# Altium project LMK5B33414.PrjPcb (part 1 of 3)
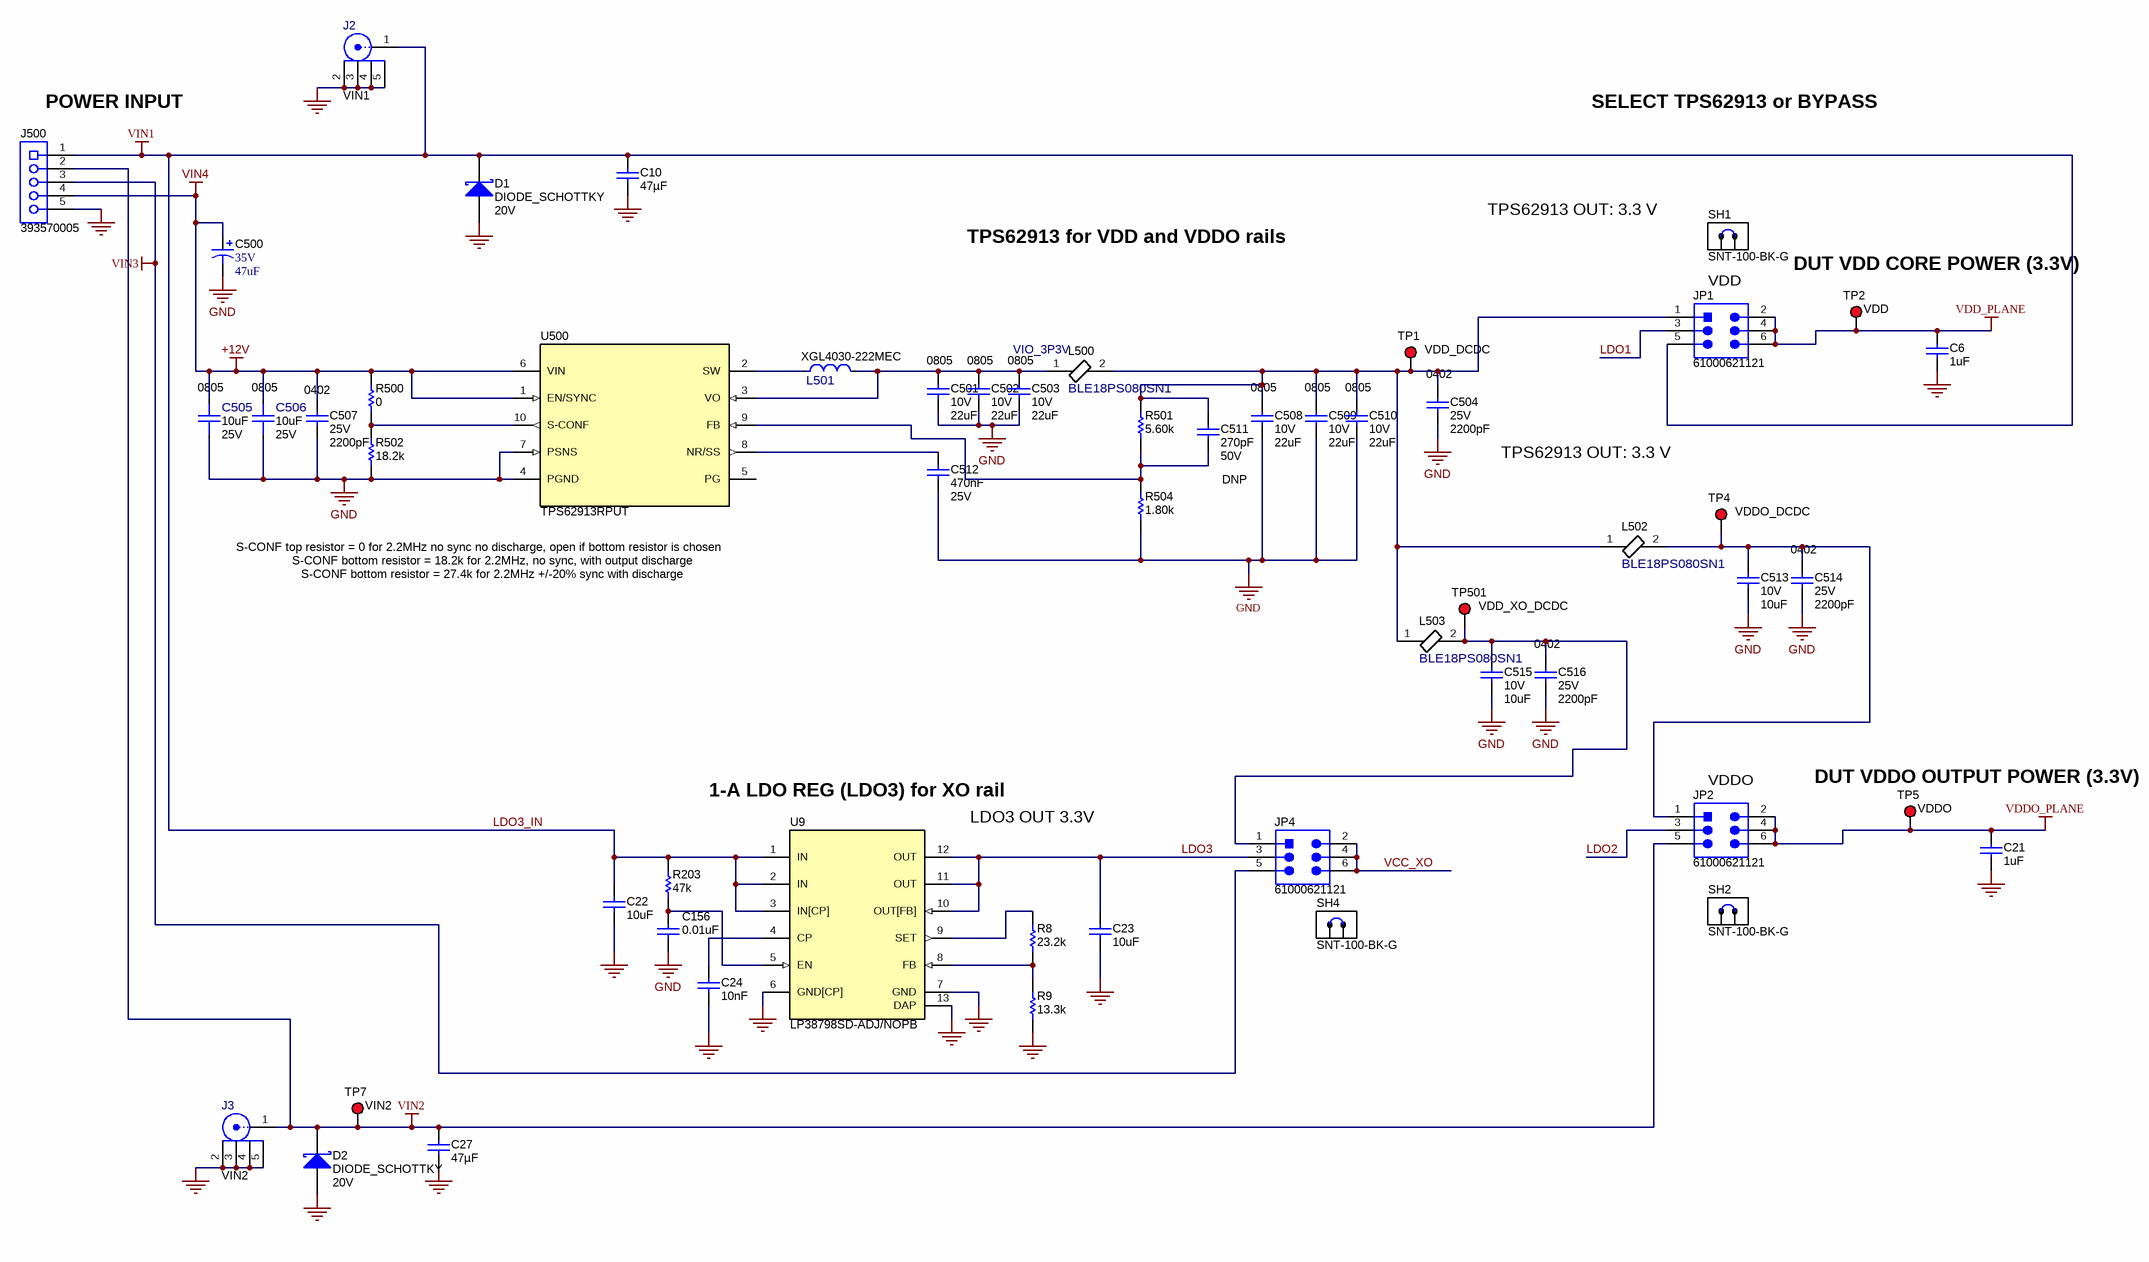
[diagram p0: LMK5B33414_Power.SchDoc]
TID: N/A; TechSupport: http://www.ti.com/support; SCH_Rev: A; PRJ_Title: LMK5B33414; PRJ_Customer: Public Release; PCB_Rev: A; CopyrightYear: 2021
11 sheets, 518 parts. Net scope: global (net labels, ports and power ports of the same name join across sheets).
Board file: LMK5B33414_PCB.PcbDoc
Sheets:
  LMK5B33414_Power.SchDoc
  LMK5B33414_Power_Alternate.SchDoc
  LMK5B33414_PowerDist.SchDoc
  LMK5B33414_DUT.SchDoc
  LMK5B33414_Logic.SchDoc
  LMK5B33414_Outputs_A.SchDoc
  LMK5B33414_Outputs_B.SchDoc
  LMK5B33414_Outputs_C.SchDoc
  LMK5B33414_XO.SchDoc
  LMK5B33414_USB2ANY.SchDoc
  LMK5B33414_Hardware.SchDoc

## Sheet LMK5B33414_Power.SchDoc
size C; Date: Not shown in title block; ApprovedBy: Not shown in title block; CheckedBy: Not shown in title block; Author: Not shown in title block; CompanyName: Not shown in title block; Engineer: Not shown in title block; Organization: Not shown in title block; Address1: Not shown in title block; Address2: Not shown in title block; Address3: Not shown in title block; Address4: Not shown in title block; DocumentNumber: 2; Revision: Use project parameter SCH_Rev; SheetNumber: 2; SheetTotal: 3; PageSetup: Record=PageOptions¦CenterHorizontal=True¦CenterVertical=True¦PrintScale=1.00¦XCorrection=1.00¦YCorrection=1.00¦PrintKind=0¦BorderSize=5000000¦LeftOffset=0¦BottomOffset=0¦Orientation=2¦PaperLength=1000¦PaperWidth=1000¦Scale=100¦PaperSource=15¦PrintQuality=600¦MediaType=1¦DitherType=10¦PaperKind=Letter¦PrintScaleMode=1

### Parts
C6  ValueDisplayed: 1uF  [0603]  (hidden comment: Capacitor)
C10  ValueDisplayed: 47µF  [0805_HV]  (hidden comment: GRM21BR61A476ME15L)
C21  ValueDisplayed: 1uF  [0603]  (hidden comment: Capacitor)
C22  ValueDisplayed: 10uF  [0603]  (hidden comment: Capacitor)
C23  ValueDisplayed: 10uF  [0603]  (hidden comment: Capacitor)
C24  ValueDisplayed: 10nF  [0603]  (hidden comment: Capacitor)
C27  ValueDisplayed: 47µF  [0805_HV]  (hidden comment: GRM21BR61A476ME15L)
C156  ValueDisplayed: 0.01uF  [0603]  (hidden comment: Capacitor)
C500  VDC_V: 35V  ValueDisplayed: 47uF  [7343-43]  (hidden comment: T495X476K035ATE300)
C501  Cap_Case: 0805  VDC_V: 10V  ValueDisplayed: 22uF  [0805L]  (hidden comment: C2012X7S1A226M125AC)
C502  Cap_Case: 0805  VDC_V: 10V  ValueDisplayed: 22uF  [0805L]  (hidden comment: C2012X7S1A226M125AC)
C503  Cap_Case: 0805  VDC_V: 10V  ValueDisplayed: 22uF  [0805L]  (hidden comment: C2012X7S1A226M125AC)
C504  VDC_V: 25V  ValueDisplayed: 2200pF  [0402]  (hidden comment: GRM155R71E222KA01D)
C505  PackageReference: 0805  ValueDisplayed: 10uF  VDC_V: 25V  [FP-C2012X7S1E106K125AC_0805-MFG]  (hidden comment: C2012X7S1E106K125AC)
C506  PackageReference: 0805  ValueDisplayed: 10uF  VDC_V: 25V  [FP-C2012X7S1E106K125AC_0805-MFG]  (hidden comment: C2012X7S1E106K125AC)
C507  VDC_V: 25V  ValueDisplayed: 2200pF  [0402]  (hidden comment: GRM155R71E222KA01D)
C508  Cap_Case: 0805  VDC_V: 10V  ValueDisplayed: 22uF  [0805L]  (hidden comment: C2012X7S1A226M125AC)
C509  Cap_Case: 0805  VDC_V: 10V  ValueDisplayed: 22uF  [0805L]  (hidden comment: C2012X7S1A226M125AC)
C510  Cap_Case: 0805  VDC_V: 10V  ValueDisplayed: 22uF  [0805L]  (hidden comment: C2012X7S1A226M125AC)
C511  Cap_F: 270pF  VDC_V: 50V  [0402]  (hidden comment: UMK105CG271JV-F)
C512  Cap_F: 470nF  VDC_V: 25V  [0603]  (hidden comment: C1608X7R1E474K080AE)
C513  VDC_V: 10V  ValueDisplayed: 10uF  [0603]  (hidden comment: GRM188Z71A106MA73D)
C514  VDC_V: 25V  ValueDisplayed: 2200pF  [0402]  (hidden comment: GRM155R71E222KA01D)
C515  VDC_V: 10V  ValueDisplayed: 10uF  [0603]  (hidden comment: GRM188Z71A106MA73D)
C516  VDC_V: 25V  ValueDisplayed: 2200pF  [0402]  (hidden comment: GRM155R71E222KA01D)
D1  DIODE_SCHOTTKY  value 20V  [SMA]
D2  DIODE_SCHOTTKY  value 20V  [SMA]
J2  VIN1  [FP-CON-SMA-EDGE-S_CONN_JACK-MFG]
J3  VIN2  [FP-CON-SMA-EDGE-S_CONN_JACK-MFG]
J500  393570005  [Molex_0393570005]
JP1  61000621121  [Wurth_61000621121]
JP2  61000621121  [Wurth_61000621121]
JP4  61000621121  [Wurth_61000621121]
L500  BLE18PS080SN1  [FP-BLE18PS080SN1_0603-MFG]
L501  XGL4030-222MEC  [FP-XGL4030-222MEC_SMT_IND_4MM0_4MM0-MFG]
L502  BLE18PS080SN1  [FP-BLE18PS080SN1_0603-MFG]
L503  BLE18PS080SN1  [FP-BLE18PS080SN1_0603-MFG]
R8  ValueDisplayed: 23.2k  [0603]  (hidden comment: CRCW060323K2FKEA)
R9  ValueDisplayed: 13.3k  [0603]  (hidden comment: CRCW060313K3FKEA)
R203  ValueDisplayed: 47k  [0603]  (hidden comment: Resistor)
R500  ValueDisplayed: 0  [0603]  (hidden comment: ERJ-3GEY0R00V)
R501  ValueDisplayed: 5.60k  [0603]  (hidden comment: RG1608P-562-B-T5)
R502  ValueDisplayed: 18.2k  [0603]  (hidden comment: CRCW060318K2FKEA)
R504  ValueDisplayed: 1.80k  [0603]  (hidden comment: RT0603BRD071K8L)
SH1  SNT-100-BK-G  [SNT-100-BK-G]
SH2  SNT-100-BK-G  [SNT-100-BK-G]
SH4  SNT-100-BK-G  [SNT-100-BK-G]
TP1  VDD_DCDC  [Keystone5000]
TP2  VDD  [Keystone5000]
TP4  VDDO_DCDC  [Keystone5000]
TP5  VDDO  [Keystone5000]
TP7  VIN2  [Keystone5000]
TP501  VDD_XO_DCDC  [Keystone5000]
U9  LP38798SD-ADJ/NOPB  [DNT0012B]
U500  TPS62913RPUT  [RPU0010A]

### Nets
+12V: C500.1(+) C505.2 C506.2 C507.1 J500.4 R500.2 U500.1(EN/SYNC) U500.6(VIN)  [also labelled VIN4]
GND: C6.1 C10.2 C21.1 C22.2 C23.2 C24.2 C27.2 C156.2 C500.2(-) C501.2 C502.2 C503.2 C504.2 C505.1 C506.1 C507.2 C508.2 C509.2 C510.2 C512.2 C513.2 C514.2 C515.2 C516.2 D1.2(A) D2.2(A) J2.2 J2.3 J2.4 J2.5 J3.2 J3.3 J3.4 J3.5 J500.5 R9.1 R502.1 R504.1 U9.6(GND[CP]) U9.7(GND) U9.13(DAP) U500.4(PGND) U500.7(PSNS)
LDO3_IN: C10.1 C22.1 D1.1(K) J2.1 J500.1 JP1.5 R203.1 U9.1(IN) U9.2(IN) U9.3(IN[CP])  [also labelled VIN1]
VCC_XO: JP4.2 JP4.4 JP4.6
VDD_PLANE: C6.2 JP1.2 JP1.4 JP1.6 TP2.1
VDDO_PLANE: C21.2 JP2.2 JP2.4 JP2.6 TP5.1
VIN2: C27.1 D2.1(K) J3.1 J500.2 JP2.5 TP7.1
VIN3: J500.3 JP4.5
LDO1: JP1.3
LDO2: JP2.3
LDO3: C23.1 JP4.3 U9.10(OUT[FB]) U9.11(OUT) U9.12(OUT)
NetC24_1: C24.1 U9.4(CP)
NetC156_1: C156.1 R203.2 U9.5(EN)
NetC501_1: C501.1 C502.1 C503.1 L500.1 L501.2 U500.3(VO)
NetC504_1: C504.1 C508.1 C509.1 C510.1 C511.1 JP1.1 L500.2 L502.1 L503.1 R501.2 TP1.1
NetC511_2: C511.2 R501.1 R504.2 U500.9(FB)
NetC512_1: C512.1 U500.8(NR/SS)
NetC513_1: C513.1 C514.1 JP2.1 L502.2 TP4.1
NetC515_1: C515.1 C516.1 JP4.1 L503.2 TP501.1
NetL501_1: L501.1 U500.2(SW)
NetR8_1: R8.1 R9.2 U9.8(FB)
NetR8_2: R8.2 U9.9(SET)
NetR500_1: R500.1 R502.2 U500.10(S-CONF)

Not connected (* = marked no-connect by the designer): U500 5(PG)

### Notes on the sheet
- (near J500) POWER INPUT
- SELECT TPS62913 or BYPASS
- TPS62913 for VDD and VDDO rails
- TPS62913 OUT: 3.3 V
- (near TP2) DUT VDD CORE POWER (3.3V)
- VDD
- VIO_3P3V
- DNP
- S-CONF top resistor = 0 for 2.2MHz no sync no discharge, open if bottom resistor is chosen
- S-CONF bottom resistor = 18.2k for 2.2MHz, no sync, with output discharge
- S-CONF bottom resistor = 27.4k for 2.2MHz +/-20% sync with discharge
- 1-A LDO REG (LDO3) for XO rail
- (near JP2) VDDO
- (near TP5) DUT VDDO OUTPUT POWER (3.3V)
- LDO3 OUT 3.3V

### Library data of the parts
C6 C21 = CMP-0006869-5: CAP, CERM, 1 uF, 10 V, +/- 10%, X5R, 0603; Manufacturer: Kemet; PartNumber: C0603C105K8PACTU; Polarized: N; TaMax_C: 85°C; TaMin_C: -55°C; VDC_V: 10V; Cap_F: 1µF; Value: 1uF; Value1: Unknown; AEC Category: Q200; SizeArea_mm2: 1.28; SizeAreaWB_mm2: 4.68; SizeX_mm: 1.6; SizeY_mm: 0.8; SizeZ_mm: 1; U/M: EA
C10 C27 = CMP-0078699-1: CAP, CERM, 47 µF, 10 V,+/- 20%, X5R, 0805; Manufacturer: MuRata; Polarized: N; Value: 47uF; U/M: EA; VDC_V: 10V; TaMin_C: -55°C; TaMax_C: 85°C; Cap_Case: 0805; SizeArea_mm2: 2.5; SizeAreaWB_mm2: 6.75; SizeX_mm: 2; SizeY_mm: 1.25; SizeZ_mm: 1.45; AEC Category: Q200; Green_Lifecycle: Active; Green_REACh: Passed
C22-C24 = CMP-0007003-5: CAP, CERM, 10 uF, 10 V, +/- 20%, X5R, 0603; PartNumber: C1608X5R1A106M080AC; Manufacturer: TDK; Polarized: N; Value: 10uF; U/M: EA; Cap_F: 10µF; ESR_ohm: 7.8m; Value1: 0.0078 ohm; VDC_V: 10V; IRMS_A: 1.85A; TaMin_C: -55°C; TaMax_C: 85°C; SizeArea_mm2: 1.28; SizeAreaWB_mm2: 4.68; SizeX_mm: 1.6; SizeY_mm: 0.8; SizeZ_mm: 1; AEC Category: Q200
C156 = CMP-0006850-4: CAP, CERM, 0.01 uF, 50 V, +/- 5%, X7R, 0603; PartNumber: C0603C103J5RACTU; Manufacturer: Kemet; Polarized: N; Value: 0.01uF; U/M: EA; Cap_F: 10nF; Value1: Unknown; VDC_V: 50V; TaMin_C: -55°C; TaMax_C: 125°C; SizeArea_mm2: 1.28; SizeAreaWB_mm2: 4.68; SizeX_mm: 1.6; SizeY_mm: 0.8; SizeZ_mm: 1; AEC Category: Q200
C500 = CMP-0011835-2: CAP, TA, 47 uF, 35 V, +/- 10%, 0.3 ohm, SMD; Manufacturer: Kemet; TaMin_C: -55°C; ESR_ohm: 3d; Polarized: Y; SizeAreaWB_mm2: 58.59; Value1: 0.3 ohm; U/M: EA; Value: 47uF; TaMax_C: 125°C; SizeZ_mm: 4.3; SizeX_mm: 7.3; Cap_Case: X; SizeArea_mm2: 31.39; CompType: Capacitor; Cap_F: 47µF; IRMS_A: 6.67dA; AEC Category: Q200
C501-C503 C508-C510 = CMP-0007890-1: CAP, CERM, 22 uF, 10 V, +/- 20%, X7S, 0805; Manufacturer: TDK; TaMin_C: -55°C; ESR_ohm: 2.05m; Polarized: N; SizeAreaWB_mm2: 6.75; Value1: 0.00205 ohm; U/M: EA; Value: 22uF; TaMax_C: 125°C; SizeZ_mm: 1.45; SizeX_mm: 2; SizeY_mm: 1.25; SizeArea_mm2: 2.5; Cap_F: 22µF; IRMS_A: 4.55587A; AEC Category: Q200
C504 C507 C514 C516 = CMP-0006663-2: CAP, CERM, 2200 pF, 25 V, +/- 10%, X7R, 0402; Manufacturer: MuRata; TaMin_C: -55°C; Polarized: N; SizeAreaWB_mm2: 3; Value1: Unknown; U/M: EA; Value: 2200pF; TaMax_C: 125°C; SizeZ_mm: 0.6; SizeX_mm: 1; SizeY_mm: 0.5; Cap_F: 2.2nF; AEC Category: Q200
C505 C506 = CMP-0089528-1: 10µF ±10% 25V Ceramic Capacitor X7S 0805 (2012 Metric); Manufacturer: TDK; TempCo: 22%; SizeZ_mm: 1.5mm; AEC Qualified: No
C511 = CMP-0087076-3: CAP CER 270PF 50V NP0 0402; Manufacturer: Taiyo Yuden; Tolerance_%: 5%; SizeZ_mm: 0.55mm; AEC Qualified: No; TempCo: 30ppm/°C
C512 = CMP-0750175-1: CAP, CERM, 0.47 µF, 25 V,+/- 10%, X7R, 0603; Manufacturer: TDK; AEC Qualified: N; TaMax_C: 125°C; U/M: EA; AEC Category: Q200; Value: 0.47uF; SizeX_mm: 1.6; SizeAreaWB_mm2: 4.68; SizeZ_mm: 1; SizeY_mm: 0.8; SizeArea_mm2: 1.28; ValueDisplayed: 0.47µF; TaMin_C: -55°C
C513 C515 = CMP-0007497-5: CAP, CERM, 10 uF, 10 V, +/- 20%, X7R, 0603; Manufacturer: MuRata; TaMin_C: -55°C; Polarized: N; SizeAreaWB_mm2: 4.68; Value1: Unknown; U/M: EA; Value: 10uF; TaMax_C: 125°C; SizeZ_mm: 1; SizeX_mm: 1.6; SizeY_mm: 0.8; SizeArea_mm2: 1.28; Cap_F: 10µF; AEC Category: Q200
D1 D2 = CMP-0028399-2: Diode, Schottky, 20 V, 2 A, SMA; PartNumber: B220A-13-F; Manufacturer: Diodes Inc.; Vf_V: 5dV; Value1: 2A; Value2: 0.5V; TJmax_C: 150°C; RJC_CperW: 20; AEC Category: Q101; Green_Lifecycle: Active; Green_REACh: Passed; SizeArea_mm2: 16.3228; SizeAreaWB_mm2: 37.3428; SizeX_mm: 5.59; SizeY_mm: 2.92; SizeZ_mm: 2.87
J2 J3 = CMP-0088000-4: CONN SMA JACK STR EDGE MNT; Manufacturer: RF Solutions Ltd.; PartNumber: CON-SMA-EDGE-S; ContactFinish: Gold; Shrouded: true
J500 = CMP-0080926-1: Terminal Block, 3.5mm, 5x1, Tin, TH; Manufacturer: Molex; Pitch_mm: 3.5; Gender: Female; Voltage_V: 300V; Row_Count: 1; Current_A: 17.5A; Cert_UL: Y
JP1 JP2 JP4 = CMP-0079534-2: Header, 2.54mm, 3x2, Gold, SMT; Manufacturer: Wurth Elektronik; Pitch_mm: 2.54; Gender: Male; Cert_UL: Y; Current_A: 3A; Voltage_V: 250V; Shrouded: N; Row_Count: 2
L500 L502 L503 = CMP-0087072-1: Bead inductor BLE series, 8A; Manufacturer: Murata; SizeZ_mm: 0.75mm; AEC Qualified: No; Material: Ferrite
L501 = CMP-0089541-1: Inductor Power Shielded Wirewound 2.2uH 20% 1MHz Composite 8.7A 15mOhm DCR Automotive T/R; Manufacturer: Coilcraft; Shrouded: true; SizeZ_mm: 3.1mm; AEC Grade: Grade 1; AEC Qualified: Yes; Isat: 3.1A; Ind_H: 2.2µH; Self Resonant Frequency: 40MHz; DCR_ohm: 0.015; Standoff Height: 0.16mm; TaMin_C: -40°C; TaMax_C: +125°C
R8 = CMP-0022228-4: RES, 23.2 k, 1%, 0.1 W, AEC-Q200 Grade 0, 0603; Manufacturer: Vishay-Dale; Value: 23.2k; Value_Code: 23k2; Power_W: 100mW; Value2: 0.1W; VDC_V: 75V; TempCo: 100 ppm/C; EIA_Code: E96; SizeArea_mm2: 1.28; SizeX_mm: 1.6; SizeY_mm: 0.8; SizeZ_mm: 1; AEC Category: Q200; AEC Qualified: Y; AEC Grade: 0
R9 = CMP-0022043-4: RES, 13.3 k, 1%, 0.1 W, AEC-Q200 Grade 0, 0603; Manufacturer: Vishay-Dale; Value: 13.3k; Value_Code: 13k3; Power_W: 100mW; Value2: 0.1W; VDC_V: 75V; TempCo: 100 ppm/C; EIA_Code: E96; SizeArea_mm2: 1.28; SizeX_mm: 1.6; SizeY_mm: 0.8; SizeZ_mm: 1; AEC Category: Q200; AEC Qualified: Y; AEC Grade: 0
R203 = CMP-0025814-4: RES, 47 k, 5%, 0.1 W, AEC-Q200 Grade 0, 0603; PartNumber: CRCW060347K0JNEA; Manufacturer: Vishay-Dale; Value: 47k; Value_Code: 47k0; Power_W: 100mW; Value2: 0.1W; VDC_V: 75V; TempCo: 200 ppm/C; EIA_Code: E24; SizeArea_mm2: 1.28; SizeX_mm: 1.6; SizeY_mm: 0.8; SizeZ_mm: 1; AEC Category: Q200; AEC Qualified: Y; AEC Grade: 0
R500 = CMP-0025874-4: RES, 0, 5%, 0.1 W, AEC-Q200 Grade 0, 0603; Manufacturer: Panasonic; Power_W: 100mW; TempCo: 600 ppm/C; Value_Code: 0000; Value: 0; EIA_Code: E24; SizeX_mm: 1.6; SizeY_mm: 0.8; SizeZ_mm: 1; Value2: 0.1W; SizeArea_mm2: 1.28; AEC Qualified: Y; VDC_V: 50V; AEC Category: Q200; SizeAreaWB_mm2: 4.68
R501 = CMP-0023576-3: RES, 5.60 k, 0.1%, 0.1 W, 0603; Manufacturer: Susumu Co Ltd; Power_W: 100mW; TempCo: 25 ppm/C; Value_Code: 5k60; U/M: EA; Value: 5.60k; Res_ohm: 5.6k; SizeX_mm: 1.6; SizeY_mm: 0.8; SizeZ_mm: 1; Value2: 0.1W; SizeArea_mm2: 1.28; VDC_V: 75V; AEC Category: Q200
R502 = CMP-0022097-4: RES, 18.2 k, 1%, 0.1 W, AEC-Q200 Grade 0, 0603; Manufacturer: Vishay-Dale; Power_W: 100mW; TempCo: 100 ppm/C; Value_Code: 18k2; Value: 18.2k; EIA_Code: E96; SizeX_mm: 1.6; SizeY_mm: 0.8; SizeZ_mm: 1; Value2: 0.1W; SizeArea_mm2: 1.28; AEC Qualified: Y; VDC_V: 75V; AEC Category: Q200; AEC Grade: 0
R504 = CMP-0023914-3: RES, 1.80 k, 0.1%, 0.1 W, 0603; Manufacturer: Yageo America; Power_W: 100mW; TempCo: 25 ppm/C; Value_Code: 1k80; U/M: EA; Value: 1.80k; EIA_Code: E192; Res_ohm: 1.8k; SizeX_mm: 1.6; SizeY_mm: 0.8; SizeZ_mm: 1; Value2: 0.1W; SizeArea_mm2: 1.28; VDC_V: 75V; AEC Category: Q200
SH1 SH2 SH4 = CMP-0003623-3: Shunt, 100mil, Gold plated, Black; Manufacturer: Samtec; Alternate Manufacturer: 3M; Alternate PartNumber: 969102-0000-DA; Value: 1x2; Note: You can "mate" this to a header by matching the designator.  i.e. use SH-J3 for header J3
TP1 TP2 TP4 TP5 TP7 TP501 = CMP-0055137-1: Test Point, Miniature, Red, TH; Manufacturer: Keystone; CNHeader: FALSE; ContactFinish: Silver; CT: TRUE; Green_Lifecycle: Active; Green_REACh: Passed
U9 = CMP-0066007-2: 800-mA Ultra-Low-Noise, High-PSRR LDO, DNT0012B (WSON-12); Manufacturer: Texas Instruments; SizeZ_mm: 0.8; SizeX_mm: 4.0; SizeArea_mm2: 16.0; CompType: IC; U/M: EA; SizeAreaWB_mm2: 25.0
U500 = CMP-0860321-2: 3A Low Noise and Low Ripple buck converter, RPU0010A (VQFN-10); Alternate Manufacturer: Texas Instruments; SizeArea_mm2: 4; SizeAreaWB_mm2: 9; AEC Category: Q200; SizeY_mm: 2; CompType: IC; SizeZ_mm: 1; AEC Qualified: N

## Sheet LMK5B33414_Power_Alternate.SchDoc
size B; Date: Not shown in title block; ApprovedBy: Not shown in title block; CheckedBy: Not shown in title block; Author: Not shown in title block; CompanyName: Not shown in title block; Engineer: Not shown in title block; Organization: Not shown in title block; Address1: Not shown in title block; Address2: Not shown in title block; Address3: Not shown in title block; Address4: Not shown in title block; DocumentNumber: 2; Revision: Use project parameter SCH_Rev; SheetNumber: 2; SheetTotal: 3; PageSetup: Record=PageOptions¦CenterHorizontal=True¦CenterVertical=True¦PrintScale=1.00¦XCorrection=1.00¦YCorrection=1.00¦PrintKind=0¦BorderSize=5000000¦LeftOffset=0¦BottomOffset=0¦Orientation=2¦PaperLength=1000¦PaperWidth=1000¦Scale=100¦PaperSource=15¦PrintQuality=600¦MediaType=1¦DitherType=10¦PaperKind=Letter¦PrintScaleMode=1
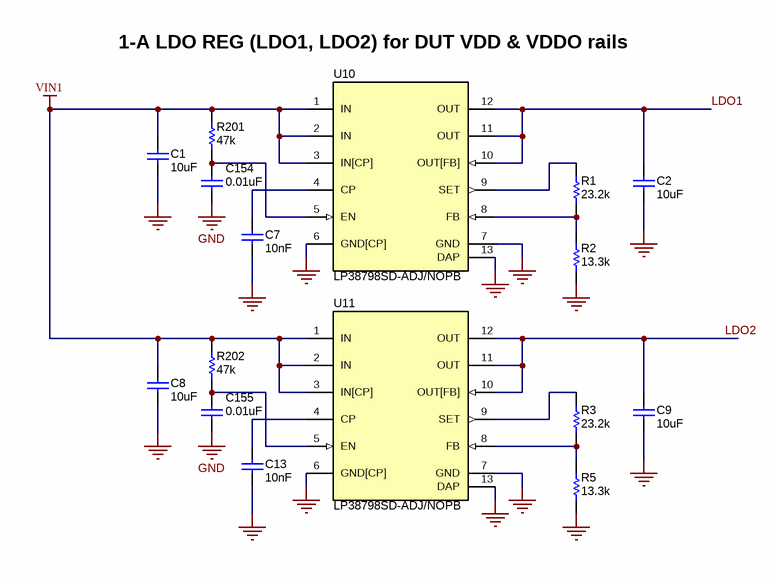
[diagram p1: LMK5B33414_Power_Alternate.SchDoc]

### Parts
C1  ValueDisplayed: 10uF  [0603]  (hidden comment: Capacitor)
C2  ValueDisplayed: 10uF  [0603]  (hidden comment: Capacitor)
C7  ValueDisplayed: 10nF  [0603]  (hidden comment: Capacitor)
C8  ValueDisplayed: 10uF  [0603]  (hidden comment: Capacitor)
C9  ValueDisplayed: 10uF  [0603]  (hidden comment: Capacitor)
C13  ValueDisplayed: 10nF  [0603]  (hidden comment: Capacitor)
C154  ValueDisplayed: 0.01uF  [0603]  (hidden comment: Capacitor)
C155  ValueDisplayed: 0.01uF  [0603]  (hidden comment: Capacitor)
R1  ValueDisplayed: 23.2k  [0603]  (hidden comment: CRCW060323K2FKEA)
R2  ValueDisplayed: 13.3k  [0603]  (hidden comment: CRCW060313K3FKEA)
R3  ValueDisplayed: 23.2k  [0603]  (hidden comment: CRCW060323K2FKEA)
R5  ValueDisplayed: 13.3k  [0603]  (hidden comment: CRCW060313K3FKEA)
R201  ValueDisplayed: 47k  [0603]  (hidden comment: Resistor)
R202  ValueDisplayed: 47k  [0603]  (hidden comment: Resistor)
U10  LP38798SD-ADJ/NOPB  [DNT0012B]
U11  LP38798SD-ADJ/NOPB  [DNT0012B]

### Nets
GND: C1.2 C2.2 C7.2 C8.2 C9.2 C13.2 C154.2 C155.2 R2.1 R5.1 U10.6(GND[CP]) U10.7(GND) U10.13(DAP) U11.6(GND[CP]) U11.7(GND) U11.13(DAP)
VIN1: C1.1 C8.1 R201.1 R202.1 U10.1(IN) U10.2(IN) U10.3(IN[CP]) U11.1(IN) U11.2(IN) U11.3(IN[CP])  [project net LDO3_IN]
LDO1: C2.1 U10.10(OUT[FB]) U10.11(OUT) U10.12(OUT)
LDO2: C9.1 U11.10(OUT[FB]) U11.11(OUT) U11.12(OUT)
NetC7_1: C7.1 U10.4(CP)
NetC13_1: C13.1 U11.4(CP)
NetC154_1: C154.1 R201.2 U10.5(EN)
NetC155_1: C155.1 R202.2 U11.5(EN)
NetR1_1: R1.1 R2.2 U10.8(FB)
NetR1_2: R1.2 U10.9(SET)
NetR3_1: R3.1 R5.2 U11.8(FB)
NetR3_2: R3.2 U11.9(SET)

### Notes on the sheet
- 1-A LDO REG (LDO1, LDO2) for DUT VDD & VDDO rails

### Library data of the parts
C1 C2 C7-C9 C13 = CMP-0007003-5: as C22 on sheet LMK5B33414_Power
C154 C155 = CMP-0006850-4: as C156 on sheet LMK5B33414_Power
R1 R3 = CMP-0022228-4: as R8 on sheet LMK5B33414_Power
R2 R5 = CMP-0022043-4: as R9 on sheet LMK5B33414_Power
R201 R202 = CMP-0025814-4: as R203 on sheet LMK5B33414_Power
U10 U11 = CMP-0066007-2: as U9 on sheet LMK5B33414_Power

## Sheet LMK5B33414_PowerDist.SchDoc
size C; Date: Not shown in title block; ApprovedBy: Not shown in title block; CheckedBy: Not shown in title block; Author: Not shown in title block; CompanyName: Not shown in title block; Engineer: Not shown in title block; Organization: Not shown in title block; Address1: Not shown in title block; Address2: Not shown in title block; Address3: Not shown in title block; Address4: Not shown in title block; DocumentNumber: 2; Revision: Use project parameter SCH_Rev; SheetNumber: 2; SheetTotal: 3; PageSetup: Record=PageOptions¦CenterHorizontal=True¦CenterVertical=True¦PrintScale=1.00¦XCorrection=1.00¦YCorrection=1.00¦PrintKind=0¦BorderSize=5000000¦LeftOffset=0¦BottomOffset=0¦Orientation=2¦PaperLength=1000¦PaperWidth=1000¦Scale=100¦PaperSource=15¦PrintQuality=600¦MediaType=1¦DitherType=10¦PaperKind=Letter¦PrintScaleMode=1
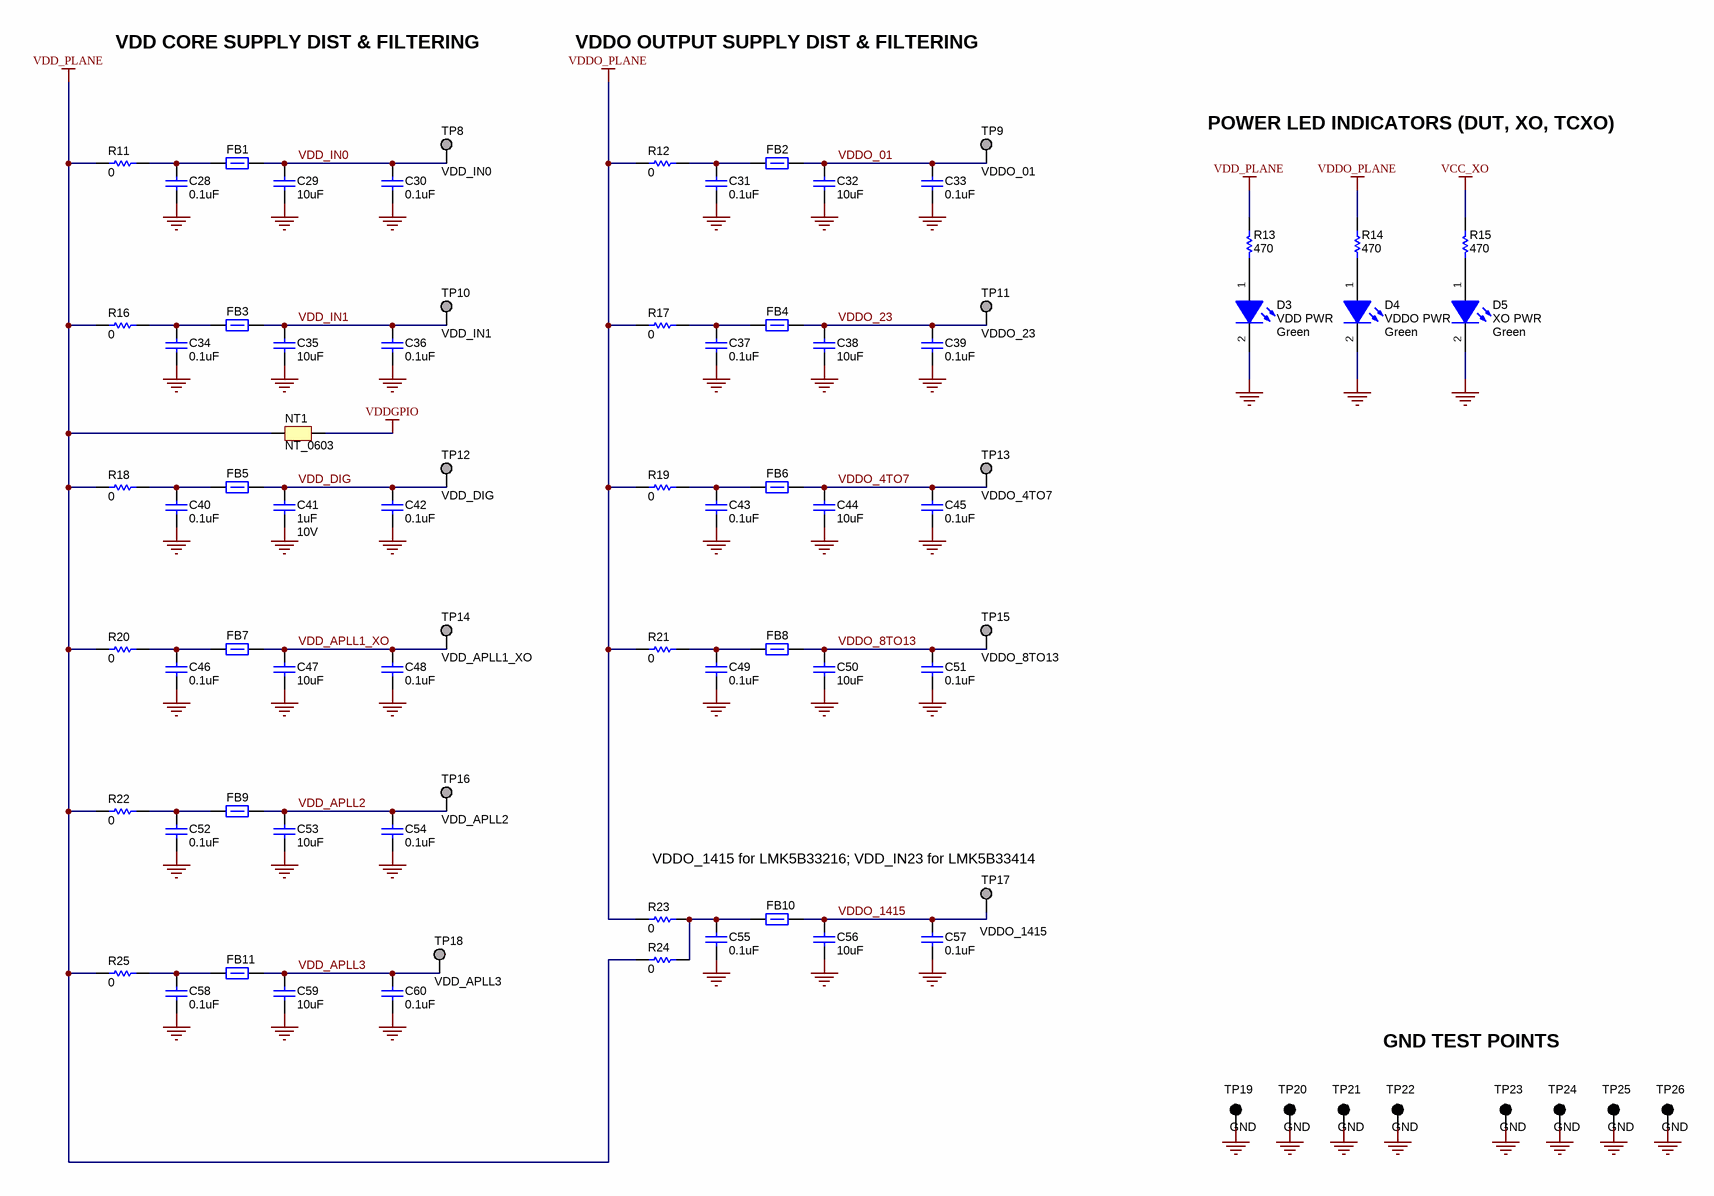
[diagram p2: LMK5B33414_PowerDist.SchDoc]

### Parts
C28  ValueDisplayed: 0.1uF  [0603L]  (hidden comment: Capacitor)
C29  ValueDisplayed: 10uF  [0603L]  (hidden comment: Capacitor)
C30  ValueDisplayed: 0.1uF  [0402L]  (hidden comment: Capacitor)
C31  ValueDisplayed: 0.1uF  [0603L]  (hidden comment: Capacitor)
C32  ValueDisplayed: 10uF  [0603L]  (hidden comment: Capacitor)
C33  ValueDisplayed: 0.1uF  [0402L]  (hidden comment: Capacitor)
C34  ValueDisplayed: 0.1uF  [0603L]  (hidden comment: Capacitor)
C35  ValueDisplayed: 10uF  [0603L]  (hidden comment: Capacitor)
C36  ValueDisplayed: 0.1uF  [0402L]  (hidden comment: Capacitor)
C37  ValueDisplayed: 0.1uF  [0603L]  (hidden comment: Capacitor)
C38  ValueDisplayed: 10uF  [0603L]  (hidden comment: Capacitor)
C39  ValueDisplayed: 0.1uF  [0402L]  (hidden comment: Capacitor)
C40  ValueDisplayed: 0.1uF  [0603L]  (hidden comment: Capacitor)
C41  ValueDisplayed: 1uF  VDC_V: 10V  [0603L]  (hidden comment: C0603C105K8PACTU)
C42  ValueDisplayed: 0.1uF  [0402L]  (hidden comment: Capacitor)
C43  ValueDisplayed: 0.1uF  [0603L]  (hidden comment: Capacitor)
C44  ValueDisplayed: 10uF  [0603L]  (hidden comment: Capacitor)
C45  ValueDisplayed: 0.1uF  [0402L]  (hidden comment: Capacitor)
C46  ValueDisplayed: 0.1uF  [0603L]  (hidden comment: Capacitor)
C47  ValueDisplayed: 10uF  [0603L]  (hidden comment: Capacitor)
C48  ValueDisplayed: 0.1uF  [0402L]  (hidden comment: Capacitor)
C49  ValueDisplayed: 0.1uF  [0603L]  (hidden comment: Capacitor)
C50  ValueDisplayed: 10uF  [0603L]  (hidden comment: Capacitor)
C51  ValueDisplayed: 0.1uF  [0402L]  (hidden comment: Capacitor)
C52  ValueDisplayed: 0.1uF  [0603L]  (hidden comment: Capacitor)
C53  ValueDisplayed: 10uF  [0603L]  (hidden comment: Capacitor)
C54  ValueDisplayed: 0.1uF  [0402L]  (hidden comment: Capacitor)
C55  ValueDisplayed: 0.1uF  [0603L]  (hidden comment: Capacitor)
C56  ValueDisplayed: 10uF  [0603L]  (hidden comment: Capacitor)
C57  ValueDisplayed: 0.1uF  [0402L]  (hidden comment: Capacitor)
C58  ValueDisplayed: 0.1uF  [0603L]  (hidden comment: Capacitor)
C59  ValueDisplayed: 10uF  [0603L]  (hidden comment: Capacitor)
C60  ValueDisplayed: 0.1uF  [0402L]  (hidden comment: Capacitor)
D3  VDD PWR  value Green  [LED_LTST-C190]
D4  VDDO PWR  value Green  [LED_LTST-C190]
D5  XO PWR  value Green  [LED_LTST-C190]
FB1  BLM18SG221TN1D  [0603L]  (value not drawn)
FB2  BLM18SG221TN1D  [0603L]  (value not drawn)
FB3  BLM18SG221TN1D  [0603L]  (value not drawn)
FB4  BLM18SG221TN1D  [0603L]  (value not drawn)
FB5  BLM18SG221TN1D  [0603L]  (value not drawn)
FB6  BLM18SG221TN1D  [0603L]  (value not drawn)
FB7  BLM18SG221TN1D  [0603L]  (value not drawn)
FB8  BLM18SG221TN1D  [0603L]  (value not drawn)
FB9  BLM18SG221TN1D  [0603L]  (value not drawn)
FB10  BLM18SG221TN1D  [0603L]  (value not drawn)
FB11  BLM18SG221TN1D  [0603L]  (value not drawn)
NT1  NT_0603  [NetTie_0603]  (net tie, no BOM)
R11  ValueDisplayed: 0  [0603]  (hidden comment: CRCW06030000Z0EA)
R12  ValueDisplayed: 0  [0603]  (hidden comment: CRCW06030000Z0EA)
R13  ValueDisplayed: 470  [0603]  (hidden comment: Resistor)
R14  ValueDisplayed: 470  [0603]  (hidden comment: Resistor)
R15  ValueDisplayed: 470  [0603]  (hidden comment: Resistor)
R16  ValueDisplayed: 0  [0603]  (hidden comment: CRCW06030000Z0EA)
R17  ValueDisplayed: 0  [0603]  (hidden comment: CRCW06030000Z0EA)
R18  ValueDisplayed: 0  [0603]  (hidden comment: CRCW06030000Z0EA)
R19  ValueDisplayed: 0  [0603]  (hidden comment: CRCW06030000Z0EA)
R20  ValueDisplayed: 0  [0603]  (hidden comment: CRCW06030000Z0EA)
R21  ValueDisplayed: 0  [0603]  (hidden comment: CRCW06030000Z0EA)
R22  ValueDisplayed: 0  [0603]  (hidden comment: CRCW06030000Z0EA)
R23  ValueDisplayed: 0  [0603]  (hidden comment: CRCW06030000Z0EA)
R24  ValueDisplayed: 0  [0603]  (hidden comment: CRCW06030000Z0EA)
R25  ValueDisplayed: 0  [0603]  (hidden comment: CRCW06030000Z0EA)
TP8  VDD_IN0  [TP_SM_1MM]  (no BOM)
TP9  VDDO_01  [TP_SM_1MM]  (no BOM)
TP10  VDD_IN1  [TP_SM_1MM]  (no BOM)
TP11  VDDO_23  [TP_SM_1MM]  (no BOM)
TP12  VDD_DIG  [TP_SM_1MM]  (no BOM)
TP13  VDDO_4TO7  [TP_SM_1MM]  (no BOM)
TP14  VDD_APLL1_XO  [TP_SM_1MM]  (no BOM)
TP15  VDDO_8TO13  [TP_SM_1MM]  (no BOM)
TP16  VDD_APLL2  [TP_SM_1MM]  (no BOM)
TP17  VDDO_1415  [TP_SM_1MM]  (no BOM)
TP18  VDD_APLL3  [TP_SM_1MM]  (no BOM)
TP19  GND  [Keystone5001]
TP20  GND  [Keystone5001]
TP21  GND  [Keystone5001]
TP22  GND  [Keystone5001]
TP23  GND  [Keystone5001]
TP24  GND  [Keystone5001]
TP25  GND  [Keystone5001]
TP26  GND  [Keystone5001]

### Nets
GND: C28.1 C29.2 C30.1 C31.1 C32.2 C33.1 C34.1 C35.2 C36.1 C37.1 C38.2 C39.1 C40.1 C41.2 C42.1 C43.1 C44.2 C45.1 C46.1 C47.2 C48.1 C49.1 C50.2 C51.1 C52.1 C53.2 C54.1 C55.1 C56.2 C57.1 C58.1 C59.2 C60.1 D3.2(K) D4.2(K) D5.2(K) TP19.1 TP20.1 TP21.1 TP22.1 TP23.1 TP24.1 TP25.1 TP26.1
VCC_XO: R15.1
VDD_PLANE: NT1.2 R11.2 R13.1 R16.2 R18.2 R20.2 R22.2 R24.1 R25.2
VDDGPIO: NT1.1
VDDO_PLANE: R12.2 R14.1 R17.2 R19.2 R21.2 R23.2
VDD_APLL1_XO: C47.1 C48.2 FB7.2 TP14.1
VDD_APLL2: C53.1 C54.2 FB9.2 TP16.1
VDD_APLL3: C59.1 C60.2 FB11.2 TP18.1
VDD_DIG: C41.1 C42.2 FB5.2 TP12.1
VDD_IN0: C29.1 C30.2 FB1.2 TP8.1
VDD_IN1: C35.1 C36.2 FB3.2 TP10.1
VDDO_01: C32.1 C33.2 FB2.2 TP9.1
VDDO_4TO7: C44.1 C45.2 FB6.2 TP13.1
VDDO_8TO13: C50.1 C51.2 FB8.2 TP15.1
VDDO_23: C38.1 C39.2 FB4.2 TP11.1
VDDO_1415: C56.1 C57.2 FB10.2 TP17.1
NetC28_2: C28.2 FB1.1 R11.1
NetC31_2: C31.2 FB2.1 R12.1
NetC34_2: C34.2 FB3.1 R16.1
NetC37_2: C37.2 FB4.1 R17.1
NetC40_2: C40.2 FB5.1 R18.1
NetC43_2: C43.2 FB6.1 R19.1
NetC46_2: C46.2 FB7.1 R20.1
NetC49_2: C49.2 FB8.1 R21.1
NetC52_2: C52.2 FB9.1 R22.1
NetC55_2: C55.2 FB10.1 R23.1 R24.2
NetC58_2: C58.2 FB11.1 R25.1
NetD3_1: D3.1(A) R13.2
NetD4_1: D4.1(A) R14.2
NetD5_1: D5.1(A) R15.2

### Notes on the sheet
- VDD CORE SUPPLY DIST & FILTERING
- VDDO OUTPUT SUPPLY DIST & FILTERING
- POWER LED INDICATORS (DUT, XO, TCXO)
- VDDO_1415 for LMK5B33216; VDD_IN23 for LMK5B33414
- GND TEST POINTS

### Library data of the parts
C28 C31 C34 C37 C40 C43 C46 C49 C52 C55 C58 = CMP-0006856-6: CAP, CERM, 0.1 uF, 25 V, +/- 5%, X7R, 0603; PartNumber: C0603C104J3RACTU; Manufacturer: Kemet; Polarized: N; Value: 0.1uF; U/M: EA; Cap_F: 100nF; Value1: Unknown; VDC_V: 25V; TaMin_C: -55°C; TaMax_C: 125°C; Cap_Case: 0603; AEC Category: Q200; SizeArea_mm2: 1.28; SizeAreaWB_mm2: 4.68; SizeX_mm: 1.6; SizeY_mm: 0.8; SizeZ_mm: 1
C29 C32 C35 C38 C44 C47 C50 C53 C56 C59 = CMP-0007003-5: CAP, CERM, 10 uF, 10 V, +/- 20%, X5R, 0603; PartNumber: C1608X5R1A106M080AC; Manufacturer: TDK; Polarized: N; Value: 10uF; U/M: EA; Cap_F: 10µF; ESR_ohm: 7.8m; Value1: 0.0078 ohm; VDC_V: 10V; IRMS_A: 1.85A; TaMin_C: -55°C; TaMax_C: 85°C; Cap_Case: 0603; SizeArea_mm2: 1.28; SizeAreaWB_mm2: 4.68; SizeX_mm: 1.6; SizeY_mm: 0.8; SizeZ_mm: 1; AEC Category: Q200
C30 C33 C36 C39 C42 C45 C48 C51 C54 C57 C60 = CMP-0006259-2: CAP, CERM, 0.1 uF, 10 V, +/- 10%, X5R, 0402; PartNumber: C1005X5R1A104K050BA; Manufacturer: TDK; Polarized: N; Value: 0.1uF; U/M: EA; Cap_F: 100nF; Value1: Unknown; VDC_V: 10V; TaMin_C: -55°C; TaMax_C: 85°C; Cap_Case: 0402; SizeArea_mm2: 0.5; SizeAreaWB_mm2: 3; SizeX_mm: 1; SizeZ_mm: 0.6; AEC Category: Q200
C41 = CMP-0006869-5: CAP, CERM, 1 uF, 10 V, +/- 10%, X5R, 0603; Manufacturer: Kemet; Polarized: N; Value: 1uF; U/M: EA; Cap_F: 1µF; Value1: Unknown; TaMin_C: -55°C; TaMax_C: 85°C; Cap_Case: 0603; SizeArea_mm2: 1.28; SizeAreaWB_mm2: 4.68; SizeX_mm: 1.6; SizeY_mm: 0.8; SizeZ_mm: 1; AEC Category: Q200
D3-D5 = CMP-0002827-3: LED, Green, SMD; Manufacturer: Lite-On; PartNumber: LTST-C190GKT; Vf_V: 2.1V; Io_A: 20mA; Power_TotalModule: 100mW; Value1: 0.1W
FB1-FB11 = CMP-0003353-2: Ferrite Bead, 220 ohm @ 100 MHz, 2.5 A, 0603; Manufacturer: MuRata; Value: 220 ohm; Imax_A: 2.5A; DCR_ohm: 0.04; Value1: 0.04 ohm; ZTyp@100MHz_Ohm: 220; SizeArea_mm2: 1.28; SizeAreaWB_mm2: 4.68; SizeX_mm: 1.6; SizeY_mm: 0.8; SizeZ_mm: 1
NT1 = CMP-0078142-3: Single point connection between nets.
R11 R12 R16-R25 = CMP-0025697-4: RES, 0, 5%, 0.1 W, AEC-Q200 Grade 0, 0603; Manufacturer: Vishay-Dale; Power_W: 100mW; TempCo: 200 ppm/C; Value_Code: 0000; Value: 0; EIA_Code: E24; SizeX_mm: 1.6; SizeY_mm: 0.8; SizeZ_mm: 1; Value2: 0.1W; SizeArea_mm2: 1.28; AEC Qualified: Y; VDC_V: 75V; AEC Category: Q200
R13-R15 = CMP-0025813-4: RES, 470, 5%, 0.1 W, AEC-Q200 Grade 0, 0603; PartNumber: CRCW0603470RJNEA; Manufacturer: Vishay-Dale; Value: 470; Value_Code: 470R; Power_W: 100mW; Value2: 0.1W; VDC_V: 75V; TempCo: 200 ppm/C; EIA_Code: E24; SizeArea_mm2: 1.28; SizeX_mm: 1.6; SizeY_mm: 0.8; SizeZ_mm: 1; AEC Category: Q200; AEC Qualified: Y; AEC Grade: 0
TP8-TP18 = CMP-0003825-1: 1mm Test Point, SMT; Manufacturer: Any
TP19-TP26 = CMP-0055138-1: Test Point, Miniature, Black, TH; Manufacturer: Keystone; ContactFinish: Silver; CNHeader: FALSE; CT: TRUE; Green_Lifecycle: Active; Green_REACh: Passed

## Sheet LMK5B33414_DUT.SchDoc
size C; Date: Not shown in title block; ApprovedBy: Not shown in title block; CheckedBy: Not shown in title block; Author: Not shown in title block; CompanyName: Not shown in title block; Engineer: Not shown in title block; Organization: Not shown in title block; Address1: Not shown in title block; Address2: Not shown in title block; Address3: Not shown in title block; Address4: Not shown in title block; DocumentNumber: 2; Revision: Use project parameter SCH_Rev; SheetNumber: 2; SheetTotal: 3; PageSetup: Record=PageOptions¦CenterHorizontal=True¦CenterVertical=True¦PrintScale=1.00¦XCorrection=1.00¦YCorrection=1.00¦PrintKind=0¦BorderSize=5000000¦LeftOffset=0¦BottomOffset=0¦Orientation=2¦PaperLength=1000¦PaperWidth=1000¦Scale=100¦PaperSource=15¦PrintQuality=600¦MediaType=1¦DitherType=10¦PaperKind=Letter¦PrintScaleMode=1
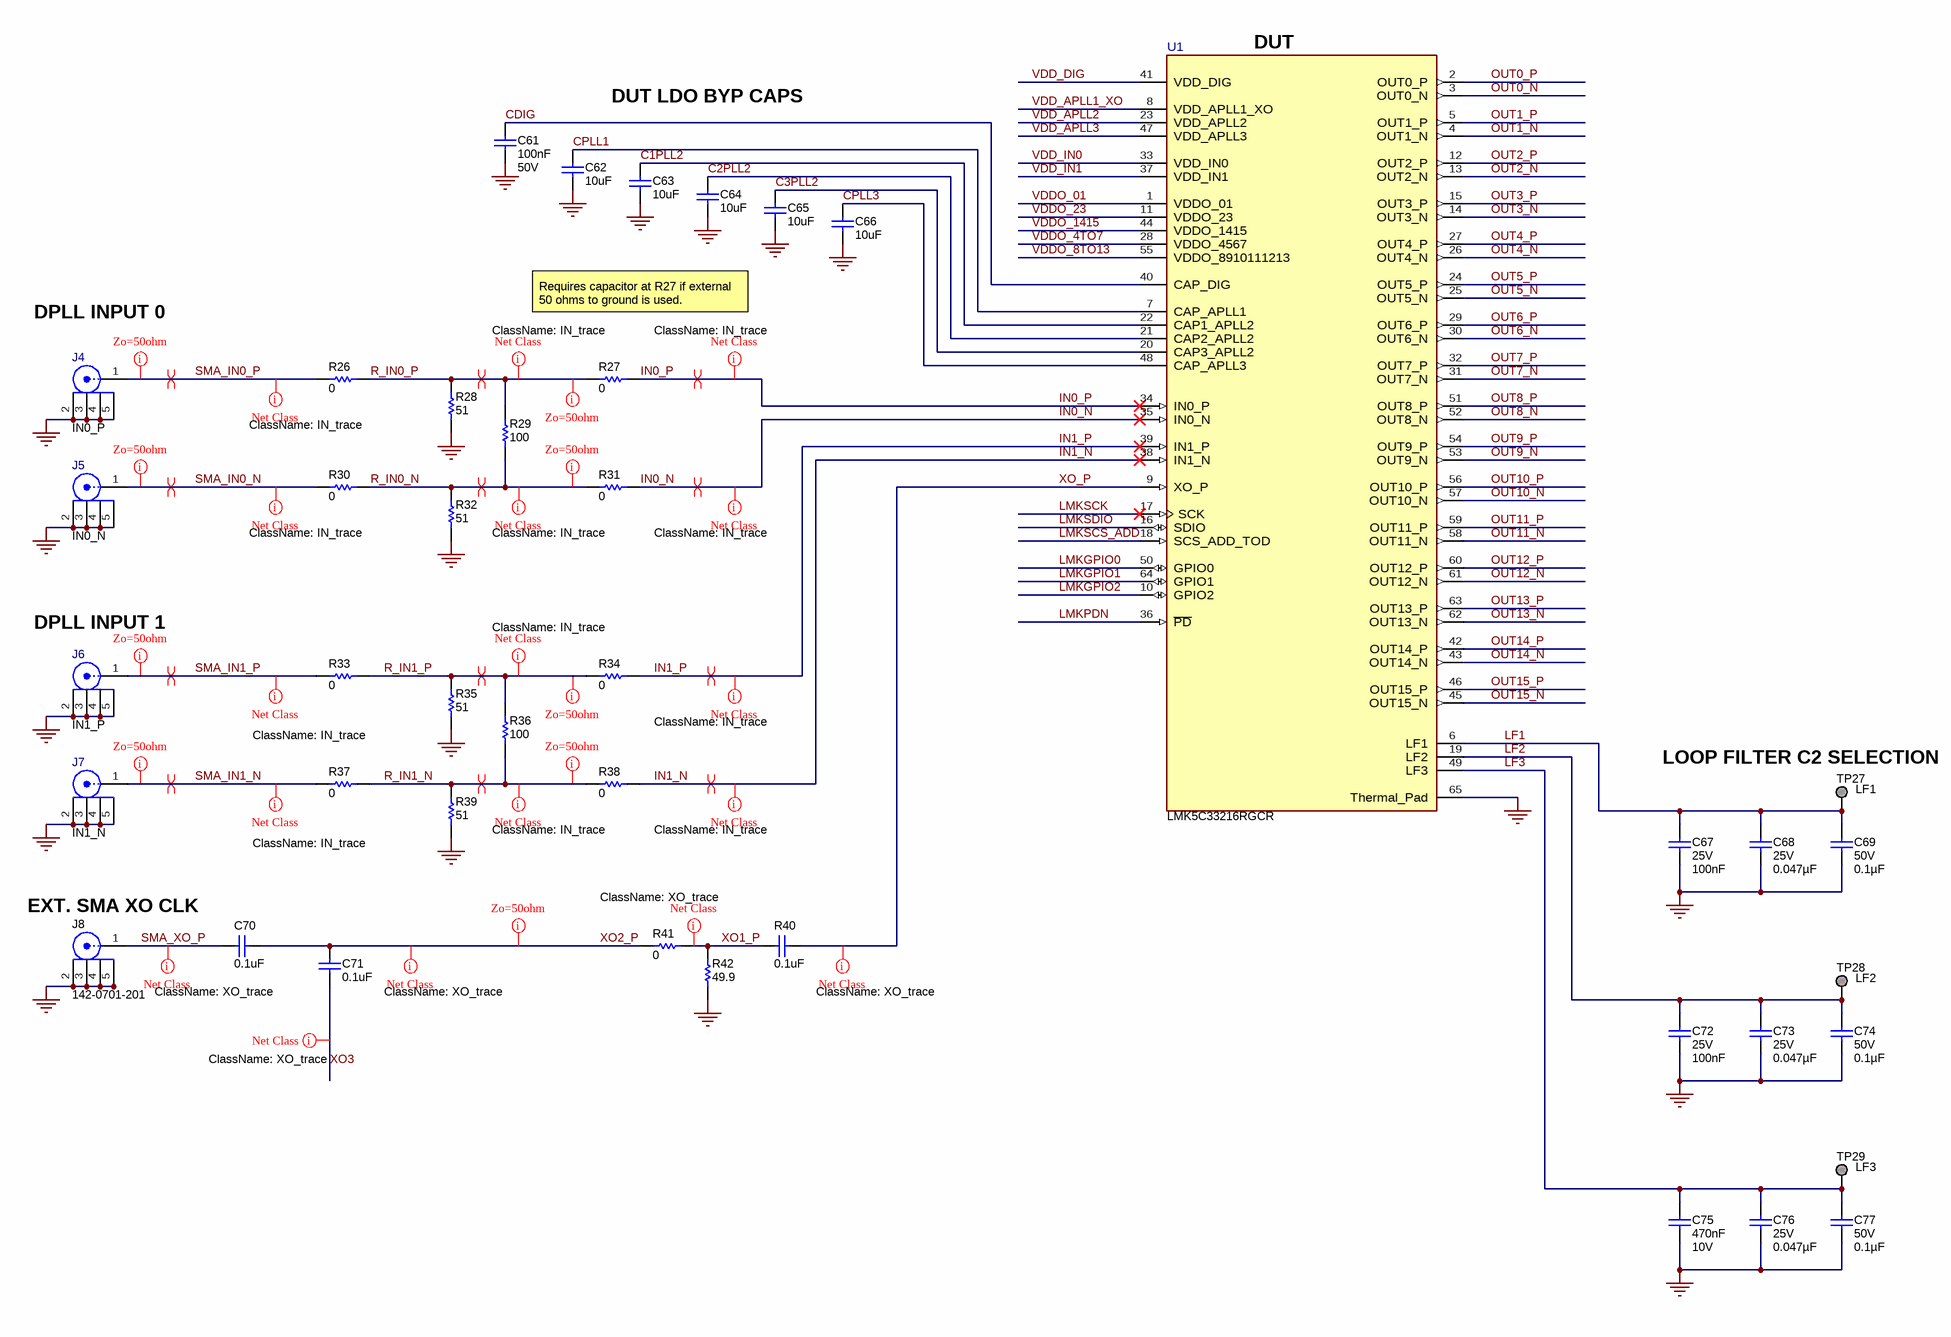
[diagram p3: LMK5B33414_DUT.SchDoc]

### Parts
C61  Cap_F: 100nF  VDC_V: 50V  [0603L]  (hidden comment: C1608X7R1H104K080AA)
C62  ValueDisplayed: 10uF  [0603L]  (hidden comment: Capacitor)
C63  ValueDisplayed: 10uF  [0603L]  (hidden comment: Capacitor)
C64  ValueDisplayed: 10uF  [0603L]  (hidden comment: Capacitor)
C65  ValueDisplayed: 10uF  [0603L]  (hidden comment: Capacitor)
C66  ValueDisplayed: 10uF  [0603L]  (hidden comment: Capacitor)
C67  VDC_V: 25V  Cap_F: 100nF  [0603]  (hidden comment: C0603C104J3RACTU)
C68  VDC_V: 25V  ValueDisplayed: 0.047µF  [0805_150]  (hidden comment: C0805C473J3GACTU)
C69  VDC_V: 50V  ValueDisplayed: 0.1µF  [1210_280]  (hidden comment: C3225C0G1H104J250AA)
C70  ValueDisplayed: 0.1uF  [0603S]  (hidden comment: C0603C104J3RACTU)
C71  ValueDisplayed: 0.1uF  [0603S]  (hidden comment: C0603C104J3RACTU)
C72  VDC_V: 25V  Cap_F: 100nF  [0603]  (hidden comment: C0603C104J3RACTU)
C73  VDC_V: 25V  ValueDisplayed: 0.047µF  [0805_150]  (hidden comment: Capacitor)
C74  VDC_V: 50V  ValueDisplayed: 0.1µF  [1210_280]  (hidden comment: C3225C0G1H104J250AA)
C75  Cap_F: 470nF  VDC_V: 10V  [0603]  (hidden comment: GRM188R71A474KA61D)
C76  VDC_V: 25V  ValueDisplayed: 0.047µF  [0805_150]  (hidden comment: Capacitor)
C77  VDC_V: 50V  ValueDisplayed: 0.1µF  [1210_280]  (hidden comment: C3225C0G1H104J250AA)
J4  IN0_P  [FP-CON-SMA-EDGE-S_CONN_JACK-MFG]
J5  IN0_N  [FP-CON-SMA-EDGE-S_CONN_JACK-MFG]
J6  IN1_P  [FP-CON-SMA-EDGE-S_CONN_JACK-MFG]
J7  IN1_N  [FP-CON-SMA-EDGE-S_CONN_JACK-MFG]
J8  142-0701-201  [Johnson_142-0701-20x]
R26  ValueDisplayed: 0  [0402L]  (hidden comment: CRCW04020000Z0EDHP)
R27  ValueDisplayed: 0  [0402L]  (hidden comment: CRCW04020000Z0EDHP)
R28  ValueDisplayed: 51  [0402S]  (hidden comment: RC0402JR-0751RL)
R29  ValueDisplayed: 100  [0603S]  (hidden comment: CRCW0603100RFKEA)
R30  ValueDisplayed: 0  [0402L]  (hidden comment: CRCW04020000Z0EDHP)
R31  ValueDisplayed: 0  [0402L]  (hidden comment: CRCW04020000Z0EDHP)
R32  ValueDisplayed: 51  [0402S]  (hidden comment: RC0402JR-0751RL)
R33  ValueDisplayed: 0  [0402L]  (hidden comment: CRCW04020000Z0EDHP)
R34  ValueDisplayed: 0  [0402L]  (hidden comment: CRCW04020000Z0EDHP)
R35  ValueDisplayed: 51  [0402S]  (hidden comment: RC0402JR-0751RL)
R36  ValueDisplayed: 100  [0603S]  (hidden comment: CRCW0603100RFKEA)
R37  ValueDisplayed: 0  [0402L]  (hidden comment: CRCW04020000Z0EDHP)
R38  ValueDisplayed: 0  [0402L]  (hidden comment: CRCW04020000Z0EDHP)
R39  ValueDisplayed: 51  [0402S]  (hidden comment: RC0402JR-0751RL)
R40  ValueDisplayed: 0.1uF  [0603S]  (hidden comment: Capacitor)
R41  value 0  [0603S]  (hidden comment: Resistor)
R42  ValueDisplayed: 49.9  [0603S]  (hidden comment: Resistor)
TP27  LF1  [TP_SM_1MM]  (no BOM)
TP28  LF2  [TP_SM_1MM]  (no BOM)
TP29  LF3  [TP_SM_1MM]  (no BOM)
U1  PartNumber: LMK5C33216RGCR  [RGC0064E-MFG]  (hidden comment: LMK05828V3RGCR)

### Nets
GND: C61.2 C62.2 C63.2 C64.2 C65.2 C66.2 C67.2 C68.1 C69.2 C72.2 C73.1 C74.2 C75.2 C76.1 C77.2 J4.2 J4.3 J4.4 J4.5 J5.2 J5.3 J5.4 J5.5 J6.2 J6.3 J6.4 J6.5 J7.2 J7.3 J7.4 J7.5 J8.2 J8.3 J8.4 J8.5 R28.1 R32.1 R35.1 R39.1 R42.1 U1.65(Thermal_Pad)
C1PLL2: C63.1 U1.22(CAP1_APLL2)
C2PLL2: C64.1 U1.21(CAP2_APLL2)
C3PLL2: C65.1 U1.20(CAP3_APLL2)
CDIG: C61.1 U1.40(CAP_DIG)
CPLL1: C62.1 U1.7(CAP_APLL1)
CPLL3: C66.1 U1.48(CAP_APLL3)
IN0_N: R31.2 U1.35(IN0_N)
IN0_P: R27.2 U1.34(IN0_P)
IN1_N: R38.2 U1.38(IN1_N)
IN1_P: R34.2 U1.39(IN1_P)
LF1: C67.1 C68.2 C69.1 TP27.1 U1.6(LF1)
LF2: C72.1 C73.2 C74.1 TP28.1 U1.19(LF2)
LF3: C75.1 C76.2 C77.1 TP29.1 U1.49(LF3)
LMKGPIO0: U1.50(GPIO0)
LMKGPIO1: U1.64(GPIO1)
LMKGPIO2: U1.10(GPIO2)
LMKPDN: U1.36(~{PD})
LMKSCK: U1.17(SCK)
LMKSCS_ADD: U1.18(SCS_ADD_TOD)
LMKSDIO: U1.16(SDIO)
OUT0_N: U1.3(OUT0_N)
OUT0_P: U1.2(OUT0_P)
OUT1_N: U1.4(OUT1_N)
OUT1_P: U1.5(OUT1_P)
OUT2_N: U1.13(OUT2_N)
OUT2_P: U1.12(OUT2_P)
OUT3_N: U1.14(OUT3_N)
OUT3_P: U1.15(OUT3_P)
OUT4_N: U1.26(OUT4_N)
OUT4_P: U1.27(OUT4_P)
OUT5_N: U1.25(OUT5_N)
OUT5_P: U1.24(OUT5_P)
OUT6_N: U1.30(OUT6_N)
OUT6_P: U1.29(OUT6_P)
OUT7_N: U1.31(OUT7_N)
OUT7_P: U1.32(OUT7_P)
OUT8_N: U1.52(OUT8_N)
OUT8_P: U1.51(OUT8_P)
OUT9_N: U1.53(OUT9_N)
OUT9_P: U1.54(OUT9_P)
OUT10_N: U1.57(OUT10_N)
OUT10_P: U1.56(OUT10_P)
OUT11_N: U1.58(OUT11_N)
OUT11_P: U1.59(OUT11_P)
OUT12_N: U1.61(OUT12_N)
OUT12_P: U1.60(OUT12_P)
OUT13_N: U1.62(OUT13_N)
OUT13_P: U1.63(OUT13_P)
OUT14_N: U1.43(OUT14_N)
OUT14_P: U1.42(OUT14_P)
OUT15_N: U1.45(OUT15_N)
OUT15_P: U1.46(OUT15_P)
R_IN0_N: R29.1 R30.2 R31.1 R32.2
R_IN0_P: R26.2 R27.1 R28.2 R29.2
R_IN1_N: R36.1 R37.2 R38.1 R39.2
R_IN1_P: R33.2 R34.1 R35.2 R36.2
SMA_IN0_N: J5.1 R30.1
SMA_IN0_P: J4.1 R26.1
SMA_IN1_N: J7.1 R37.1
SMA_IN1_P: J6.1 R33.1
SMA_XO_P: C70.1 J8.1
VDD_APLL1_XO: U1.8(VDD_APLL1_XO)
VDD_APLL2: U1.23(VDD_APLL2)
VDD_APLL3: U1.47(VDD_APLL3)
VDD_DIG: U1.41(VDD_DIG)
VDD_IN0: U1.33(VDD_IN0)
VDD_IN1: U1.37(VDD_IN1)
VDDO_01: U1.1(VDDO_01)
VDDO_4TO7: U1.28(VDDO_4567)
VDDO_8TO13: U1.55(VDDO_8910111213)
VDDO_23: U1.11(VDDO_23)
VDDO_1415: U1.44(VDDO_1415)
XO1_P: R40.1 R41.2 R42.2
XO2_P: C70.2 C71.1 R41.1
XO3: C71.2
XO_P: R40.2 U1.9(XO_P)

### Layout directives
rule Impedance Constraint [Min = 45.00    Max = 55.00    ]: R_IN0_N, R_IN0_P, R_IN1_N, R_IN1_P, SMA_IN0_N, SMA_IN0_P, SMA_IN1_N, SMA_IN1_P, XO2_P
differential pair: IN0_N, IN0_P, IN1_N, IN1_P, R_IN0_N, R_IN0_P, R_IN1_N, R_IN1_P, SMA_IN0_N, SMA_IN0_P, SMA_IN1_N, SMA_IN1_P
net class XO_trace: SMA_XO_P, XO1_P, XO2_P, XO3, XO_P
net class IN_trace: IN0_N, IN0_P, IN1_N, IN1_P, R_IN0_N, R_IN0_P, R_IN1_N, R_IN1_P, SMA_IN0_N, SMA_IN0_P, SMA_IN1_N, SMA_IN1_P

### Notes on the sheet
- (near U1) DUT
- DUT LDO BYP CAPS
- DPLL INPUT 0
- Requires capacitor at R27 if external 50 ohms to ground is used.
- (near J6) DPLL INPUT 1
- (near TP27) LOOP FILTER C2 SELECTION
- (near J8) EXT. SMA XO CLK

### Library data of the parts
C61 = CMP-0007044-5: CAP, CERM, 0.1 uF, 50 V, +/- 10%, X7R, 0603; Manufacturer: TDK; Polarized: N; Value: 0.1uF; U/M: EA; ESR_ohm: 0.0296; Value1: 0.0296 ohm; IRMS_A: 9.7199dA; TaMin_C: -55°C; TaMax_C: 125°C; Cap_Case: 0603; SizeArea_mm2: 1.28; SizeAreaWB_mm2: 4.68; SizeX_mm: 1.6; SizeY_mm: 0.8; SizeZ_mm: 1; AEC Category: Q200
C62-C66 = CMP-0007003-5: as C29 on sheet LMK5B33414_PowerDist
C67 C72 = CMP-0006856-6: CAP, CERM, 0.1 uF, 25 V, +/- 5%, X7R, 0603; Manufacturer: Kemet; Polarized: N; TaMax_C: 125°C; TaMin_C: -55°C; Value: 0.1uF; Value1: Unknown; U/M: EA; AEC Category: Q200; SizeArea_mm2: 1.28; SizeAreaWB_mm2: 4.68; SizeX_mm: 1.6; SizeY_mm: 0.8; SizeZ_mm: 1
C68 = CMP-0078743-1: CAP, CERM, 0.047 µF, 25 V,+/- 5%, C0G/NP0, AEC-Q200 Grade 1, 0805; Manufacturer: Kemet; Polarized: N; TaMax_C: 125°C; TaMin_C: -55°C; Cap_F: 47nF; Value: 0.047uF; U/M: EA; SizeArea_mm2: 2.5; SizeAreaWB_mm2: 6.75; SizeX_mm: 2; SizeY_mm: 1.25; SizeZ_mm: 1.5; AEC Category: Q200; AEC Qualified: Y; AEC Grade: 1; Green_REACh: Incomplete; Green_Lifecycle: Not Set
C69 C74 C77 = CMP-0081101-1: CAP, CERM, 0.1 µF, 50 V,+/- 5%, C0G/NP0, 1210; Manufacturer: TDK; TaMin_C: -55°C; Polarized: N; SizeAreaWB_mm2: 14.7; U/M: EA; Value: 0.1uF; TaMax_C: 125°C; SizeZ_mm: 2.8; SizeX_mm: 3.2; SizeY_mm: 2.5; Cap_Case: 1210; SizeArea_mm2: 8; Cap_F: 100nF; AEC Category: Q200; Green_Lifecycle: Active; Green_REACh: Incomplete
C70 C71 = CMP-0006856-6: CAP, CERM, 0.1 uF, 25 V, +/- 5%, X7R, 0603; Manufacturer: Kemet; TaMin_C: -55°C; Polarized: N; SizeAreaWB_mm2: 4.68; Value1: Unknown; U/M: EA; Value: 0.1uF; TaMax_C: 125°C; SizeZ_mm: 1; SizeX_mm: 1.6; SizeY_mm: 0.8; Cap_Case: 0603; Value2: 25V; SizeArea_mm2: 1.28; Cap_F: 100nF; AEC Category: Q200
C73 C76 = CMP-0078743-1: CAP, CERM, 0.047 µF, 25 V,+/- 5%, C0G/NP0, AEC-Q200 Grade 1, 0805; Manufacturer: Kemet; PartNumber: C0805C473J3GACTU; Polarized: N; TaMax_C: 125°C; TaMin_C: -55°C; Cap_F: 47nF; Value: 0.047uF; U/M: EA; SizeArea_mm2: 2.5; SizeAreaWB_mm2: 6.75; SizeX_mm: 2; SizeY_mm: 1.25; SizeZ_mm: 1.5; AEC Category: Q200; AEC Qualified: Y; AEC Grade: 1; Green_REACh: Incomplete; Green_Lifecycle: Not Set
C75 = CMP-0007373-4: CAP, CERM, 0.47 uF, 10 V, +/- 10%, X7R, 0603; Manufacturer: MuRata; Polarized: N; Value: 0.47uF; U/M: EA; Value1: Unknown; TaMin_C: -55°C; TaMax_C: 125°C; SizeArea_mm2: 1.28; SizeAreaWB_mm2: 4.68; SizeX_mm: 1.6; SizeY_mm: 0.8; SizeZ_mm: 1; AEC Category: Q200
J4-J7 = CMP-0088000-4: as J2 on sheet LMK5B33414_Power
J8 = CMP-0055819-1: Connector, SMA, TH; Manufacturer: Cinch Connectivity; CNHeader: FALSE; CT: TRUE; Green_Lifecycle: Not Set; Green_REACh: Incomplete
R26 R30 R31 R33 R34 R37 R38 = CMP-0081856-1: RES, 0, 0%, 0.2 W, AEC-Q200 Grade 0, 0402; Manufacturer: Vishay-Dale; VDC_V: 50V; Power_W: 200mW; Value: 0; Value2: 0.2W; AEC Category: Q200; AEC Qualified: Y; SizeArea_mm2: 0.5; SizeX_mm: 1; SizeZ_mm: 0.6; SizeAreaWB_mm2: 3
R27 = CMP-0081856-1: RES, 0, 0%, 0.2 W, AEC-Q200 Grade 0, 0402; Manufacturer: Vishay-Dale; CompType: Resistor; VDC_V: 50V; Power_W: 200mW; Value: 0; Value2: 0.2W; AEC Category: Q200; AEC Qualified: Y; SizeArea_mm2: 0.5; SizeX_mm: 1; SizeZ_mm: 0.6; SizeAreaWB_mm2: 3
R28 R32 R35 R39 = CMP-0027006-2: RES, 51, 5%, 0.0625 W, 0402; Manufacturer: Yageo America; Value: 51; Value_Code: 51R0; Power_W: 62.5mW; VDC_V: 50V; TempCo: 100 ppm/C; EIA_Code: E24; AEC Category: Q200; AEC Qualified: N; SizeArea_mm2: 0.5; SizeX_mm: 1; SizeZ_mm: 0.6; U/M: EA
R29 R36 = CMP-0021991-4: RES, 100, 1%, 0.1 W, AEC-Q200 Grade 0, 0603; Manufacturer: Vishay-Dale; Value: 100; Value_Code: 100R; Power_W: 100mW; Value2: 0.1W; VDC_V: 75V; TempCo: 100 ppm/C; EIA_Code: E96; AEC Category: Q200; AEC Qualified: Y; AEC Grade: 0; SizeArea_mm2: 1.28; SizeX_mm: 1.6; SizeY_mm: 0.8; SizeZ_mm: 1
R40 = CMP-0006856-6: CAP, CERM, 0.1 uF, 25 V, +/- 5%, X7R, 0603; Manufacturer: Kemet; PartNumber: C0603C104J3RACTU; VDC_V: 25V; Value: 0.1uF; Value1: Unknown; U/M: EA; Polarized: N; Cap_F: 100nF; TaMin_C: -55°C; TaMax_C: 125°C; Cap_Case: 0603; SizeArea_mm2: 1.28; SizeAreaWB_mm2: 4.68; SizeX_mm: 1.6; SizeY_mm: 0.8; SizeZ_mm: 1; AEC Category: Q200
R41 = CMP-0025697-4: RES, 0, 5%, 0.1 W, AEC-Q200 Grade 0, 0603; Manufacturer: Vishay-Dale; PartNumber: CRCW06030000Z0EA; VDC_V: 75V; Power_W: 100mW; Value_Code: 0000; Value2: 0.1W; EIA_Code: E24; TempCo: 200 ppm/C; AEC Category: Q200; AEC Qualified: Y; SizeArea_mm2: 1.28; SizeX_mm: 1.6; SizeY_mm: 0.8; SizeZ_mm: 1
R42 = CMP-0022448-4: RES, 49.9, 1%, 0.1 W, AEC-Q200 Grade 0, 0603; PartNumber: CRCW060349R9FKEA; Manufacturer: Vishay-Dale; Value: 49.9; Value_Code: 49R9; Power_W: 100mW; Value2: 0.1W; VDC_V: 75V; TempCo: 100 ppm/C; EIA_Code: E96; AEC Category: Q200; AEC Qualified: Y; AEC Grade: 0; SizeArea_mm2: 1.28; SizeX_mm: 1.6; SizeY_mm: 0.8; SizeZ_mm: 1
TP27-TP29 = CMP-0003825-1: 1mm Test Point, SMT; Manufacturer: Any
U1 = CMP-0088768-1: Ultra-Low Jitter Clock Synchronizer with JESD204B for Wireless Communications; Manufacturer: Texas Instruments; Max Supply Voltage: 3.465V; AEC Qualified: No; Interface: I2C,SPI; Number Of Outputs: 16; Standoff Height: 0mm; TJmax_C: +135°C; Max Frequency: 2.94912GHz; Min Supply Voltage: 3.135V; Pll: YES; SizeZ_mm: 1mm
